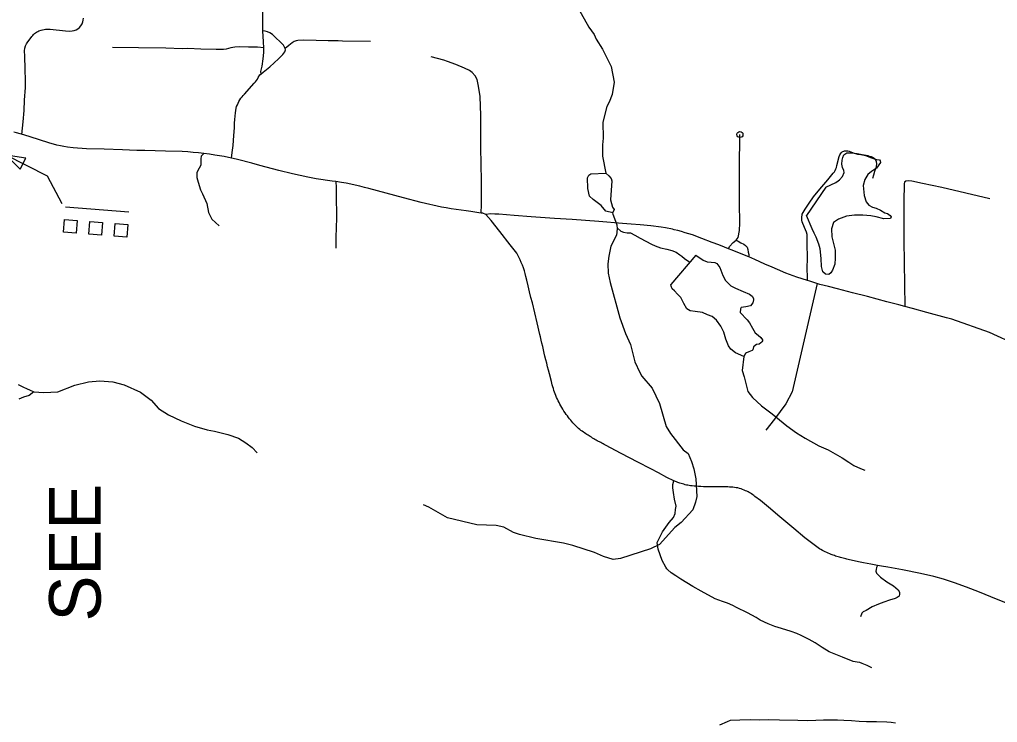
# Model space of a CAD drawing. Extents: x -19 to 366, y -4 to 359.
# Drawn here: x 139.407 to 140.926, y 192.02 to 193.112 of the extents above; entities that cross this region are included whole.
import ezdxf

# ---------------------------------------------------------------- set-up
doc = ezdxf.new("R2010")
doc.units = 0
for name, color, linetype in [('21', 7, 'Continuous'), ('Level 19', 7, 'Continuous'), ('R_ROW', 7, 'Continuous'), ('R_ROW Annot', 7, 'Continuous'), ('R_Temp Easement', 7, 'Continuous'), ('Sheet Fence', 7, 'Continuous')]:
    doc.layers.add(name, color=color, linetype=linetype)

msp = doc.modelspace()

# ---------------------------------------------------------------- linework, layer by layer
at = {"layer": '21'}
for points in [[(139.4736, 192.8257), (139.4508, 192.8686), (139.3869, 192.9011)], [(139.5772, 192.8126), (139.4786, 192.8206)]]:
    msp.add_lwpolyline(points, dxfattribs=at)
for points in [[(139.4083, 192.8794), (139.4171, 192.8966), (139.3869, 192.9011)], [(139.4755, 192.7816), (139.4771, 192.8013), (139.4968, 192.7997), (139.4952, 192.78)], [(139.5149, 192.7784), (139.5165, 192.7981), (139.5362, 192.7965), (139.5346, 192.7768)], [(139.5543, 192.7752), (139.5559, 192.7949), (139.5756, 192.7933), (139.574, 192.7736)]]:
    msp.add_lwpolyline(points, close=True, dxfattribs=at)
at = {"layer": 'R_ROW'}
for points in [[(139.7854, 193.0942), (139.7852, 193.1136), (139.7854, 193.1286), (139.7854, 193.1463)], [(139.4111, 192.9334), (139.413, 192.9527), (139.4144, 192.9703), (139.4153, 192.9868), (139.4167, 193.006), (139.4165, 193.017), (139.4162, 193.0345), (139.4154, 193.055), (139.4153, 193.0633), (139.4157, 193.0671), (139.4168, 193.0707), (139.4184, 193.0741), (139.4195, 193.0758), (139.4266, 193.0855), (139.4279, 193.0871), (139.4292, 193.0886), (139.4307, 193.0899), (139.4323, 193.0912), (139.434, 193.0923), (139.4357, 193.0933), (139.4375, 193.0942), (139.4408, 193.0954), (139.4431, 193.096), (139.4455, 193.0964), (139.4478, 193.0968), (139.4502, 193.0969), (139.4525, 193.0969), (139.4549, 193.0968), (139.4789, 193.0943), (139.4856, 193.0939), (139.4889, 193.094), (139.4922, 193.0946), (139.4953, 193.0958), (139.4981, 193.0975), (139.5006, 193.0996), (139.5028, 193.1022), (139.5046, 193.1051), (139.5059, 193.1083), (139.5064, 193.1108), (139.5065, 193.1139)], [(139.7867, 193.0677), (139.7864, 193.0771), (139.7854, 193.0942)], [(139.8201, 193.067), (139.8172, 193.0719), (139.8113, 193.0781), (139.8063, 193.0825), (139.8, 193.0883), (139.7963, 193.0909), (139.7924, 193.0927), (139.7888, 193.0938), (139.7854, 193.0942)], [(139.7827, 193.0275), (139.7823, 193.0309), (139.784, 193.0396), (139.7857, 193.0508), (139.7866, 193.0605), (139.7867, 193.0677)], [(139.7827, 193.0275), (139.7859, 193.0298), (139.7959, 193.0382), (139.8095, 193.0505), (139.8163, 193.0576), (139.8192, 193.0614), (139.8202, 193.0647), (139.8201, 193.067)], [(139.9522, 193.0777), (139.9088, 193.0782), (139.9024, 193.0786), (139.8864, 193.0788), (139.868, 193.0791), (139.8479, 193.0796), (139.8393, 193.0792), (139.8367, 193.0789), (139.8338, 193.0779), (139.8306, 193.0758), (139.8254, 193.0714), (139.8201, 193.067)], [(140.1243, 192.8111), (140.1248, 192.8245), (140.1246, 192.8611), (140.1236, 192.9131), (140.1236, 192.9629), (140.1224, 192.9923), (140.1203, 193.0082), (140.1182, 193.0189), (140.1151, 193.0242), (140.1101, 193.0297), (140.1063, 193.0328), (140.0984, 193.0365), (140.0847, 193.042), (140.0721, 193.0465), (140.0662, 193.0485), (140.0464, 193.0536)], [(139.7366, 192.8964), (139.7378, 192.9055), (139.7389, 192.916), (139.7403, 192.9317), (139.741, 192.9438), (139.7414, 192.951), (139.7419, 192.9565), (139.7429, 192.9668), (139.7436, 192.9741), (139.7445, 192.9768), (139.7456, 192.9795), (139.7468, 192.9821), (139.7481, 192.9846), (139.7496, 192.9871), (139.7512, 192.9895), (139.753, 192.9918), (139.7548, 192.9939), (139.7566, 192.9959), (139.7719, 193.013), (139.7737, 193.015), (139.7753, 193.0171), (139.7768, 193.0194), (139.7782, 193.0217), (139.7803, 193.0258), (139.7827, 193.0275)], [(139.5944, 192.9084), (139.5897, 192.9086), (139.5781, 192.9091), (139.5675, 192.9092), (139.5386, 192.9102), (139.5115, 192.9111), (139.5045, 192.9114), (139.4975, 192.9119), (139.4905, 192.9125), (139.4819, 192.9135), (139.4764, 192.9144), (139.4709, 192.9155), (139.4654, 192.9167), (139.46, 192.9181), (139.4547, 192.9196), (139.4369, 192.9252), (139.4255, 192.9289), (139.4141, 192.9325), (139.4027, 192.936), (139.3988, 192.9371)], [(140.5203, 192.7693), (140.5234, 192.773), (140.5255, 192.7843), (140.5257, 192.7955), (140.5254, 192.8265), (140.5252, 192.8587), (140.5251, 192.8808), (140.5255, 192.8963), (140.526, 192.9177), (140.5259, 192.9332)], [(139.6934, 192.9037), (139.6854, 192.9047), (139.6769, 192.9055), (139.6685, 192.9062), (139.6601, 192.9067), (139.6343, 192.9073), (139.6021, 192.9082), (139.5944, 192.9084)], [(139.7366, 192.8964), (139.7321, 192.8975), (139.725, 192.8989), (139.718, 192.9001), (139.7105, 192.9013), (139.7022, 192.9026), (139.6934, 192.9037)], [(140.6307, 192.7064), (140.6309, 192.7139), (140.6306, 192.7232), (140.6309, 192.7438), (140.6304, 192.7614), (140.6306, 192.7778), (140.6295, 192.7817), (140.6264, 192.7887), (140.6225, 192.7974), (140.6221, 192.8), (140.622, 192.8037), (140.6228, 192.8096), (140.6272, 192.8175), (140.6336, 192.8268), (140.6404, 192.8363), (140.6503, 192.8481), (140.6626, 192.863), (140.671, 192.8732), (140.6726, 192.8752), (140.6739, 192.8774), (140.675, 192.8798), (140.6758, 192.8822), (140.6764, 192.8849), (140.6802, 192.8988), (140.6812, 192.9017), (140.6834, 192.9048), (140.6849, 192.9061), (140.6884, 192.9077), (140.691, 192.9079), (140.6934, 192.9077), (140.6958, 192.9072), (140.698, 192.9064), (140.7018, 192.905), (140.7083, 192.9028), (140.7136, 192.9019), (140.7188, 192.9013), (140.7219, 192.9011), (140.7245, 192.9005), (140.7269, 192.8996), (140.7296, 192.8988), (140.732, 192.8978), (140.7344, 192.8964), (140.7358, 192.8948), (140.7376, 192.8914), (140.7381, 192.8876), (140.7376, 192.8837), (140.7369, 192.8813), (140.7352, 192.8759), (140.7332, 192.8698), (140.732, 192.8651)], [(139.8986, 192.8601), (139.893, 192.8609), (139.8682, 192.8643), (139.8549, 192.8668), (139.8314, 192.872), (139.81, 192.8775), (139.7803, 192.8853), (139.7683, 192.8885), (139.746, 192.8942), (139.739, 192.8959), (139.7366, 192.8964)], [(140.1243, 192.8111), (140.1205, 192.8116), (140.1143, 192.8125), (140.1084, 192.8135), (140.1007, 192.8145), (140.093, 192.8155), (140.0852, 192.8167), (140.0775, 192.8179), (140.0698, 192.8192), (140.0625, 192.8205), (140.0312, 192.8274), (140.0037, 192.8346), (139.9498, 192.8492), (139.9428, 192.8511), (139.9358, 192.853), (139.9287, 192.8546), (139.9216, 192.8562), (139.9145, 192.8576), (139.9074, 192.8588), (139.8986, 192.8601)], [(140.1317, 192.8092), (140.1267, 192.8108), (140.1243, 192.8111)], [(140.5082, 192.7558), (140.5023, 192.7582), (140.4932, 192.7618), (140.4831, 192.7654), (140.467, 192.7718), (140.4521, 192.7774), (140.4411, 192.7807), (140.4354, 192.7823), (140.4297, 192.7839), (140.424, 192.7854), (140.4214, 192.7861), (140.4105, 192.7882), (140.4035, 192.7894), (140.3874, 192.7911), (140.3713, 192.7927), (140.357, 192.794), (140.3438, 192.7951), (140.3068, 192.798), (140.2655, 192.801), (140.2383, 192.8028), (140.2019, 192.8052), (140.1757, 192.8074), (140.1515, 192.8093), (140.1453, 192.8094), (140.139, 192.8098), (140.1317, 192.8092)], [(140.4236, 192.3952), (140.4214, 192.3962), (140.4191, 192.3972), (140.4168, 192.3984), (140.4145, 192.3995), (140.4124, 192.4006), (140.3998, 192.4076), (140.3877, 192.4137), (140.3675, 192.4241), (140.3417, 192.4379), (140.3172, 192.4507), (140.3154, 192.4517), (140.3135, 192.4526), (140.3117, 192.4536), (140.3098, 192.4546), (140.308, 192.4556), (140.3062, 192.4566), (140.3044, 192.4576), (140.3026, 192.4586), (140.3008, 192.4597), (140.299, 192.4607), (140.2972, 192.4618), (140.2954, 192.4629), (140.2936, 192.464), (140.2919, 192.4651), (140.2901, 192.4662), (140.2883, 192.4673), (140.2866, 192.4685), (140.2849, 192.4696), (140.2829, 192.471), (140.281, 192.4723), (140.2792, 192.4737), (140.2773, 192.4752), (140.2755, 192.4767), (140.2738, 192.4783), (140.2721, 192.4799), (140.2704, 192.4815), (140.2685, 192.4835), (140.2667, 192.4855), (140.2649, 192.4875), (140.2632, 192.4896), (140.2614, 192.4917), (140.2598, 192.4938), (140.2582, 192.496), (140.2563, 192.4985), (140.2545, 192.5011), (140.2528, 192.5037), (140.2511, 192.5064), (140.2495, 192.5091), (140.2479, 192.5118), (140.2465, 192.5143), (140.2452, 192.5169), (140.2439, 192.5196), (140.2426, 192.5222), (140.2414, 192.5249), (140.2403, 192.5276), (140.2392, 192.5303), (140.2382, 192.533), (140.2372, 192.5358), (140.2363, 192.5385), (140.2355, 192.5413), (140.2347, 192.5442), (140.2333, 192.5496), (140.2302, 192.5615), (140.2288, 192.567), (140.2274, 192.5724), (140.226, 192.5779), (140.2247, 192.5834), (140.2233, 192.5888), (140.2221, 192.5938), (140.2209, 192.5989), (140.2197, 192.6039), (140.2185, 192.6089), (140.2174, 192.6139), (140.2162, 192.6189), (140.2154, 192.6226), (140.211, 192.6409), (140.2038, 192.6715), (140.2014, 192.6803), (140.1992, 192.6891), (140.197, 192.698), (140.195, 192.7068), (140.1938, 192.7127), (140.1926, 192.7171), (140.1913, 192.7215), (140.1899, 192.7259), (140.1883, 192.7302), (140.1865, 192.7345), (140.1847, 192.7387), (140.1827, 192.7429), (140.1805, 192.7469), (140.1794, 192.7489), (140.1694, 192.7619), (140.1531, 192.7828), (140.1399, 192.7997), (140.1317, 192.8092)], [(140.5082, 192.7558), (140.5098, 192.7593), (140.5153, 192.7654), (140.5203, 192.7693)], [(140.5203, 192.7693), (140.5233, 192.7677), (140.5272, 192.7649), (140.5322, 192.7628), (140.5346, 192.761), (140.537, 192.7584), (140.5382, 192.7546), (140.5389, 192.7503), (140.5397, 192.7469), (140.5396, 192.7431)], [(140.5396, 192.7431), (140.5281, 192.7478), (140.514, 192.7535), (140.5082, 192.7558)], [(140.6307, 192.7064), (140.6141, 192.7116), (140.5972, 192.7179), (140.5841, 192.7233), (140.5758, 192.7269), (140.5649, 192.7318), (140.5491, 192.739), (140.5396, 192.7431)], [(140.782, 192.6661), (140.7726, 192.6685), (140.7542, 192.6735), (140.724, 192.6814), (140.7007, 192.6874), (140.6776, 192.6935), (140.6633, 192.6973), (140.6502, 192.7004), (140.6344, 192.7052), (140.6307, 192.7064)], [(140.646, 192.7016), (140.607, 192.5333), (140.5974, 192.5148), (140.5795, 192.4912), (140.566, 192.4739)], [(141.3538, 192.6581), (141.3107, 192.596), (141.304, 192.588), (141.296, 192.5811), (141.2871, 192.5757), (141.2774, 192.5717), (141.2672, 192.5693), (141.2568, 192.5685), (141.0876, 192.5683), (141.0809, 192.5683), (141.053, 192.5702), (141.0257, 192.5762), (140.9995, 192.5862), (140.9137, 192.6256), (140.855, 192.6464), (140.8467, 192.6486), (140.816, 192.657), (140.7942, 192.6628), (140.782, 192.6661)], [(140.731, 192.1048), (140.7237, 192.1082), (140.716, 192.1115), (140.7121, 192.1131), (140.7081, 192.1136), (140.7019, 192.1148), (140.6855, 192.1212), (140.6645, 192.1299), (140.6539, 192.1364), (140.6426, 192.1434), (140.6336, 192.149), (140.6212, 192.1552), (140.6141, 192.1584), (140.6056, 192.1614), (140.5907, 192.1658), (140.5801, 192.1692), (140.5699, 192.1733), (140.5573, 192.179), (140.551, 192.1828), (140.538, 192.1901), (140.5209, 192.1987), (140.515, 192.2017), (140.5068, 192.2053), (140.4989, 192.2081), (140.4875, 192.2122), (140.4657, 192.2239), (140.453, 192.2311), (140.4342, 192.2426), (140.4266, 192.2476), (140.4193, 192.2525), (140.4138, 192.257), (140.4126, 192.2588), (140.411, 192.2612), (140.4053, 192.2715), (140.3992, 192.289), (140.3976, 192.2997), (140.4059, 192.3161), (140.416, 192.3304), (140.4229, 192.3384), (140.4252, 192.3444), (140.4262, 192.3505), (140.4268, 192.356), (140.4243, 192.3669), (140.4227, 192.3772), (140.422, 192.3845), (140.4219, 192.3894), (140.4236, 192.3952)], [(140.7396, 192.264), (140.7291, 192.2658), (140.7177, 192.2679), (140.7101, 192.2693), (140.6942, 192.2729), (140.6922, 192.2734), (140.6902, 192.2739), (140.6882, 192.2744), (140.6863, 192.275), (140.6843, 192.2755), (140.6823, 192.2761), (140.6804, 192.2767), (140.6784, 192.2773), (140.6764, 192.2779), (140.6745, 192.2785), (140.6726, 192.2792), (140.6706, 192.2798), (140.6679, 192.2808), (140.6655, 192.2817), (140.6632, 192.2827), (140.6608, 192.2838), (140.6585, 192.2849), (140.6562, 192.286), (140.654, 192.2872), (140.6517, 192.2885), (140.6495, 192.2898), (140.6474, 192.2912), (140.6452, 192.2926), (140.6431, 192.2941), (140.6266, 192.3068), (140.6095, 192.3212), (140.5879, 192.3396), (140.5706, 192.3544), (140.5582, 192.3645), (140.5494, 192.3711), (140.5477, 192.3724), (140.5459, 192.3737), (140.5441, 192.3749), (140.5423, 192.376), (140.5405, 192.3771), (140.5386, 192.3781), (140.5366, 192.3791), (140.5347, 192.38), (140.5327, 192.3809), (140.5301, 192.382), (140.5277, 192.3828), (140.5252, 192.3836), (140.5227, 192.3842), (140.5202, 192.3846), (140.5177, 192.385), (140.5151, 192.3852), (140.5125, 192.3855), (140.5099, 192.3857), (140.5073, 192.3858), (140.4851, 192.3861), (140.4812, 192.386), (140.4773, 192.386), (140.4734, 192.3861), (140.4695, 192.3862), (140.4655, 192.3863), (140.4616, 192.3865), (140.4577, 192.3868), (140.4552, 192.387), (140.4518, 192.3873), (140.4495, 192.3876), (140.4473, 192.3879), (140.4451, 192.3883), (140.443, 192.3888), (140.4408, 192.3893), (140.4387, 192.3899), (140.4366, 192.3905), (140.4345, 192.3912), (140.4325, 192.3919), (140.4298, 192.3929), (140.4274, 192.3937), (140.4236, 192.3952)], [(140.7396, 192.264), (140.738, 192.2606), (140.7376, 192.2576), (140.7369, 192.2549), (140.7383, 192.2517), (140.7441, 192.2455), (140.7542, 192.2386), (140.7647, 192.232), (140.7715, 192.2261), (140.7736, 192.2222), (140.774, 192.2193), (140.7733, 192.2163), (140.7704, 192.2142), (140.7673, 192.2124), (140.7582, 192.2099), (140.7497, 192.2067), (140.7412, 192.2035), (140.7315, 192.1995), (140.7218, 192.194), (140.7172, 192.1917), (140.7155, 192.1896), (140.7132, 192.1839)], [(140.9568, 192.1985), (140.9244, 192.2116), (140.898, 192.2224), (140.8776, 192.2302), (140.859, 192.2368), (140.842, 192.2425), (140.8273, 192.2469), (140.8066, 192.2514), (140.7786, 192.2568), (140.7558, 192.261), (140.7458, 192.2629), (140.7396, 192.264)], [(140.7675, 192.0189), (140.7609, 192.0201), (140.7542, 192.0206), (140.7382, 192.0208), (140.7223, 192.0211), (140.7111, 192.0215), (140.6994, 192.0223), (140.6875, 192.0228), (140.6774, 192.0236), (140.6688, 192.0237), (140.6556, 192.0233), (140.6438, 192.023), (140.6311, 192.0227), (140.616, 192.0231), (140.5875, 192.0236), (140.571, 192.0242), (140.5565, 192.0237), (140.5424, 192.0238), (140.526, 192.0233), (140.5106, 192.023), (140.5061, 192.0211), (140.4944, 192.016)]]:
    msp.add_lwpolyline(points, dxfattribs=at)
msp.add_circle((140.5259, 192.9332), 0.00473, dxfattribs=at)
at = {"layer": 'R_ROW Annot'}
for points in [[(139.7867, 193.0677), (139.777, 193.0687), (139.7628, 193.0687), (139.7483, 193.0695), (139.7415, 193.0688), (139.7354, 193.0679), (139.7281, 193.0657), (139.724, 193.0651), (139.7129, 193.065), (139.6891, 193.0658), (139.6688, 193.0666), (139.66, 193.0664), (139.6345, 193.0671), (139.5921, 193.0678), (139.552, 193.0683)], [(139.6934, 192.9037), (139.6896, 192.8997), (139.689, 192.8952), (139.6887, 192.8855), (139.6863, 192.881), (139.6828, 192.8741), (139.6825, 192.8665), (139.6846, 192.859), (139.6883, 192.8471), (139.6914, 192.8412), (139.6983, 192.8258), (139.7007, 192.8121), (139.7061, 192.8019), (139.7174, 192.7912)], [(139.8986, 192.8601), (139.8988, 192.8511), (139.8989, 192.8314), (139.8996, 192.8128), (139.8994, 192.8014), (139.8991, 192.791), (139.8986, 192.7713), (139.8984, 192.7566)], [(140.9142, 192.8334), (140.8397, 192.8509), (140.8095, 192.8569), (140.793, 192.8608), (140.7871, 192.8612), (140.7836, 192.8606), (140.7817, 192.859), (140.7808, 192.8565), (140.7806, 192.8294), (140.7805, 192.7686), (140.782, 192.6661)]]:
    msp.add_lwpolyline(points, dxfattribs=at)
at = {"layer": 'R_Temp Easement'}
for points in [[(140.2702, 193.1376), (140.2915, 193.1001), (140.2995, 193.0884), (140.3029, 193.0812), (140.3124, 193.0657), (140.3262, 193.0388), (140.3308, 193.0145), (140.3275, 192.9952), (140.323, 192.9834), (140.3192, 192.9766), (140.3129, 192.9526), (140.3134, 192.9276), (140.3127, 192.917), (140.3124, 192.8995), (140.3178, 192.873), (140.3223, 192.8692), (140.3261, 192.8651), (140.3273, 192.8613), (140.3251, 192.832), (140.3282, 192.8203), (140.3305, 192.8165), (140.3283, 192.8108), (140.3348, 192.793), (140.3355, 192.7869), (140.3341, 192.7767), (140.3258, 192.7596), (140.3225, 192.744), (140.321, 192.7323), (140.3215, 192.7178), (140.3246, 192.7034), (140.3395, 192.6485), (140.3483, 192.6242)], [(140.6594, 192.8513), (140.6751, 192.8588), (140.6786, 192.861), (140.6806, 192.8627), (140.6852, 192.868), (140.6881, 192.8741), (140.6875, 192.8775), (140.6855, 192.8818), (140.6842, 192.8871), (140.6848, 192.8932), (140.6859, 192.8976), (140.6873, 192.9016), (140.6921, 192.9047), (140.6995, 192.9049), (140.7082, 192.9039), (140.7183, 192.9015), (140.7288, 192.8977), (140.7381, 192.8945), (140.7425, 192.8939), (140.7438, 192.8924), (140.7442, 192.8899), (140.738, 192.8809), (140.7304, 192.8758), (140.7247, 192.8709), (140.7197, 192.8634), (140.7175, 192.8539), (140.7188, 192.8386), (140.7218, 192.8284), (140.7261, 192.8234), (140.732, 192.8203), (140.7376, 192.8189), (140.7441, 192.8156), (140.7511, 192.8118), (140.7553, 192.8105), (140.7594, 192.8076), (140.7609, 192.8052), (140.7597, 192.8025), (140.7497, 192.8021), (140.7375, 192.8054), (140.7291, 192.8067), (140.7168, 192.808), (140.704, 192.8077), (140.6916, 192.8063), (140.6788, 192.8017), (140.6714, 192.7964), (140.6682, 192.7868), (140.6689, 192.7741), (140.6714, 192.7641), (140.6741, 192.7536), (140.6738, 192.7409), (140.6732, 192.7319), (140.6697, 192.7224), (140.6673, 192.7182), (140.6642, 192.716), (140.6587, 192.7161), (140.6548, 192.72), (140.6529, 192.7283), (140.6523, 192.7406), (140.6504, 192.7555), (140.6485, 192.7627), (140.6443, 192.7736), (140.6415, 192.7802), (140.6382, 192.7865), (140.6292, 192.8074)], [(140.3286, 192.8116), (140.318, 192.8142), (140.3104, 192.8229), (140.2979, 192.8323), (140.2922, 192.8372), (140.2899, 192.8494), (140.2895, 192.8657), (140.2913, 192.8702), (140.2943, 192.8721), (140.3178, 192.873)], [(140.6594, 192.8513), (140.6292, 192.8074)], [(140.3353, 192.7885), (140.3411, 192.783), (140.3454, 192.7816), (140.3508, 192.7804), (140.3562, 192.7803), (140.3627, 192.7769), (140.3713, 192.7723), (140.3798, 192.7676), (140.3889, 192.7628), (140.3943, 192.7601), (140.4025, 192.7571), (140.4124, 192.7552), (140.4203, 192.7531), (140.427, 192.7502), (140.4328, 192.7464), (140.4357, 192.744), (140.4401, 192.7406), (140.4483, 192.7348)], [(140.4574, 192.7456), (140.4687, 192.7379), (140.475, 192.7354), (140.4812, 192.7349), (140.4869, 192.7343), (140.4903, 192.7328), (140.495, 192.7265), (140.4994, 192.7143), (140.5038, 192.7066), (140.5121, 192.6981), (140.5192, 192.6944), (140.5312, 192.6892), (140.5407, 192.6854), (140.5452, 192.6819), (140.5469, 192.6787), (140.5472, 192.6763), (140.546, 192.6719), (140.5425, 192.6669), (140.5353, 192.6654), (140.528, 192.6643), (140.5267, 192.6626), (140.5263, 192.6565), (140.5371, 192.6451), (140.541, 192.6407), (140.5455, 192.6324), (140.5495, 192.6253), (140.5543, 192.6213), (140.5583, 192.6177), (140.5611, 192.6142), (140.5609, 192.6125), (140.5598, 192.611), (140.5583, 192.6094), (140.5559, 192.6075), (140.5516, 192.6068), (140.5473, 192.6033), (140.5459, 192.5989), (140.5448, 192.5979), (140.5396, 192.5955), (140.5362, 192.5939), (140.5347, 192.593), (140.532, 192.5882), (140.5192, 192.5941), (140.5121, 192.5999), (140.508, 192.6051), (140.504, 192.6154), (140.5009, 192.6261), (140.4965, 192.6355), (140.4895, 192.645), (140.4828, 192.6504), (140.4759, 192.6531), (140.4681, 192.6565), (140.4563, 192.6583), (140.4487, 192.6595), (140.4438, 192.6624), (140.439, 192.6707), (140.4343, 192.68), (140.4293, 192.6854), (140.4242, 192.6904), (140.421, 192.6934), (140.4193, 192.6977), (140.4189, 192.7)], [(140.4574, 192.7456), (140.4189, 192.7)], [(140.3483, 192.6242), (140.356, 192.6072), (140.3629, 192.5799), (140.3705, 192.5636), (140.3739, 192.5579), (140.3895, 192.5394), (140.4013, 192.5152), (140.4117, 192.4799), (140.4182, 192.469), (140.4379, 192.4436), (140.4455, 192.4376), (140.4509, 192.4255), (140.4543, 192.4141), (140.4574, 192.3982), (140.4591, 192.3709), (140.4572, 192.3621), (140.4531, 192.35), (140.4346, 192.3306), (140.4248, 192.3229), (140.4011, 192.2963), (140.3872, 192.2898), (140.3407, 192.2744), (140.3294, 192.2729), (140.3142, 192.2777), (140.3002, 192.2841), (140.2665, 192.295), (140.2518, 192.2987), (140.209, 192.3058), (140.1837, 192.3118), (140.1746, 192.3148), (140.1594, 192.3231), (140.1473, 192.326), (140.1174, 192.3267), (140.072, 192.3379), (140.0432, 192.3545), (140.0349, 192.3582)], [(140.532, 192.5882), (140.5297, 192.5669), (140.5325, 192.5569), (140.5352, 192.5467), (140.5384, 192.5339), (140.5454, 192.5246), (140.5595, 192.5116), (140.576, 192.4995), (140.5989, 192.4808), (140.6139, 192.4698), (140.6275, 192.4615), (140.6485, 192.4499), (140.6632, 192.4432), (140.6845, 192.4309), (140.695, 192.4245), (140.7031, 192.4192), (140.7132, 192.4143), (140.7201, 192.412)], [(139.4294, 192.5333), (139.4451, 192.5326), (139.4668, 192.5337), (139.4934, 192.5441), (139.5147, 192.5488), (139.5321, 192.5508), (139.5521, 192.5489), (139.57, 192.5446), (139.595, 192.5332), (139.6116, 192.5208), (139.6234, 192.5076), (139.6387, 192.4976), (139.6586, 192.4887), (139.6792, 192.4801), (139.6988, 192.4746), (139.7102, 192.4724), (139.7311, 192.467), (139.7473, 192.4613), (139.7586, 192.4543), (139.7685, 192.4471), (139.7765, 192.4388)], [(139.4053, 192.5448), (139.4127, 192.5413), (139.4191, 192.5383), (139.4228, 192.5366), (139.4294, 192.5333), (139.4223, 192.5276), (139.4137, 192.5251), (139.4064, 192.522)]]:
    msp.add_lwpolyline(points, dxfattribs=at)
at = {"layer": 'Sheet Fence'}
for points in [[(146.7783, 1.697), (146.5788, 10.3131), (146.3785, 18.9294), (146.1776, 27.5458), (145.9759, 36.1624), (145.7736, 44.7791), (145.5705, 53.396), (145.3668, 62.013), (145.1624, 70.6301), (144.9572, 79.2474), (144.7514, 87.8648), (144.5449, 96.4823), (144.3377, 105.1), (144.1299, 113.7179), (143.9213, 122.3359), (143.712, 130.954), (143.5021, 139.5723), (143.2915, 148.1907), (143.0802, 156.8092), (142.8682, 165.4279), (142.6555, 174.0468), (142.4422, 182.6658), (142.2282, 191.2849), (142.0135, 199.9042), (141.7981, 208.5236), (141.582, 217.1432), (141.3653, 225.7629), (141.1479, 234.3828), (140.9298, 243.0028), (140.711, 251.623), (140.4916, 260.2433), (140.2715, 268.8638), (140.0508, 277.4844), (139.8293, 286.1051), (139.6072, 294.726), (139.3845, 303.3471), (139.161, 311.9683), (138.937, 320.5896), (138.7122, 329.2111), (138.4868, 337.8328), (138.2607, 346.4546)], [(139.4406, 1.5315), (139.2511, 10.1473), (139.0608, 18.7633), (138.8699, 27.3793), (138.6784, 35.9956), (138.4861, 44.6119), (138.2932, 53.2285), (138.0997, 61.8451), (137.9055, 70.4619), (137.7106, 79.0789), (137.5151, 87.6959), (137.319, 96.3132), (137.1221, 104.9306), (136.9247, 113.5481), (136.7265, 122.1658), (136.5278, 130.7836), (136.3283, 139.4016), (136.1282, 148.0197), (135.9275, 156.6379), (135.7261, 165.2564), (135.5241, 173.8749), (135.3214, 182.4936), (135.1181, 191.1125), (134.9141, 199.7315), (134.7095, 208.3506), (134.5043, 216.9699), (134.2984, 225.5894), (134.0919, 234.209), (133.8847, 242.8288), (133.6769, 251.4487), (133.4685, 260.0687), (133.2594, 268.6889), (133.0497, 277.3093), (132.8393, 285.9298), (132.6283, 294.5504), (132.4167, 303.1713), (132.2044, 311.7922), (131.9916, 320.4133), (131.778, 329.0346), (131.5639, 337.656), (131.3491, 346.2776)], [(0, 189.5162), (7.1121, 189.5206), (14.2243, 189.5339), (21.3364, 189.556), (28.4484, 189.5869), (35.5605, 189.6267), (42.6725, 189.6754), (49.7844, 189.7329), (56.8962, 189.7992), (64.0079, 189.8744), (71.1196, 189.9584), (78.2311, 190.0512), (85.3425, 190.1529), (92.4538, 190.2635), (99.5649, 190.3829), (106.6759, 190.5111), (113.7867, 190.6482), (120.8974, 190.7941), (128.0078, 190.9489), (135.1181, 191.1125), (142.2282, 191.2849), (149.338, 191.4662), (156.4476, 191.6563), (163.5569, 191.8553), (170.666, 192.0631), (177.7749, 192.2798), (184.8835, 192.5053), (191.9917, 192.7396), (199.0997, 192.9828), (206.2074, 193.2348), (213.3147, 193.4956), (220.4218, 193.7653), (227.5285, 194.0438), (234.6348, 194.3312), (241.7408, 194.6274), (248.8464, 194.9324), (255.9516, 195.2463), (263.0564, 195.569), (270.1608, 195.9005), (277.2648, 196.2409), (284.3683, 196.5901), (291.4715, 196.9481), (298.5741, 197.315), (305.6763, 197.6907), (312.7781, 198.0753), (319.8793, 198.4686), (326.9801, 198.8708), (334.0804, 199.2818), (341.1801, 199.7017)]]:
    msp.add_spline(points, degree=3, dxfattribs=at)

# ---------------------------------------------------------------- texts
at = {"layer": 'Level 19'}
msp.add_text('SEE', height=0.08, rotation=90.0518, dxfattribs=at).set_placement((139.5334, 192.1768))

doc.saveas('drawing.dxf')
